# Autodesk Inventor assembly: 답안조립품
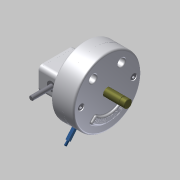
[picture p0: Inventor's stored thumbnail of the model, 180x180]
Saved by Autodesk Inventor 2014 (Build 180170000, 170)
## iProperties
Created: 2015-04
Part Number: 답안조립품
Document SubType Name: Assembly
Designer: Administrator
Mass: 3964.99 g
Surface Area: 3333.71 cm^2
Volume: 1140.85 cm^3
Density: 3.47547 g/cm^3
Author: Administrator
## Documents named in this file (15)
- C:\Documents and Settings\Administrator\바탕 화면\350406V1016\답안조립품.iam
- C:\Documents and Settings\Administrator\바탕 화면\350406V1016\본체.ipt
- C:\Documents and Settings\Administrator\바탕 화면\350406V1016\커버.ipt
- C:\Documents and Settings\Administrator\바탕 화면\350406V1016\커버2.ipt
- C:\Documents and Settings\Administrator\바탕 화면\350406V1016\M 10 x 35.ipt
- C:\Documents and Settings\Administrator\바탕 화면\350406V1016\M 5 x 12.ipt
- C:\Documents and Settings\Administrator\바탕 화면\350406V1016\부시.ipt
- C:\Documents and Settings\Administrator\바탕 화면\350406V1016\슬라이더3.ipt
- C:\Documents and Settings\Administrator\바탕 화면\350406V1016\축.ipt
- C:\Documents and Settings\Administrator\바탕 화면\350406V1016\멈춤링.ipt
- C:\Documents and Settings\Administrator\바탕 화면\350406V1016\베어링62_22.ipt
- C:\Documents and Settings\Administrator\바탕 화면\350406V1016\가변스프링.ipt
- C:\Documents and Settings\Administrator\바탕 화면\350406V1016\슬라이더2.ipt
- C:\Documents and Settings\Administrator\바탕 화면\350406V1016\슬라이더.ipt
- C:\Documents and Settings\Administrator\바탕 화면\350406V1016\평행핀.ipt
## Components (6 placed, 4 different names)
1. M 10 x 35:1
2. M 10 x 35:2
3. M 5 x 12:1
4. M 5 x 12:2
5. 가변스프링:1
6. KS B 1320 B B 5 x  20:1 — 플러쉬:1
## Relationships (1: Flush 1)
- 플러쉬:1 [Flush]: KS B 1320 B B 5 x  20:1
